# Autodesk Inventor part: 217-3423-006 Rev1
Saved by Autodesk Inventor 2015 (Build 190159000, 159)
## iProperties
Created: 2014-11
Part Number: 217-3423-006 Rev1
Material: Generic
Document SubType Name: Modeling
Designer: User
Density: 1 g/cm^3
Appearance: Default
Author: User
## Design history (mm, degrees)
node "217-3423-006 Rev1.ipt1"
node "Boss-Extrude1"
node "Base1"
